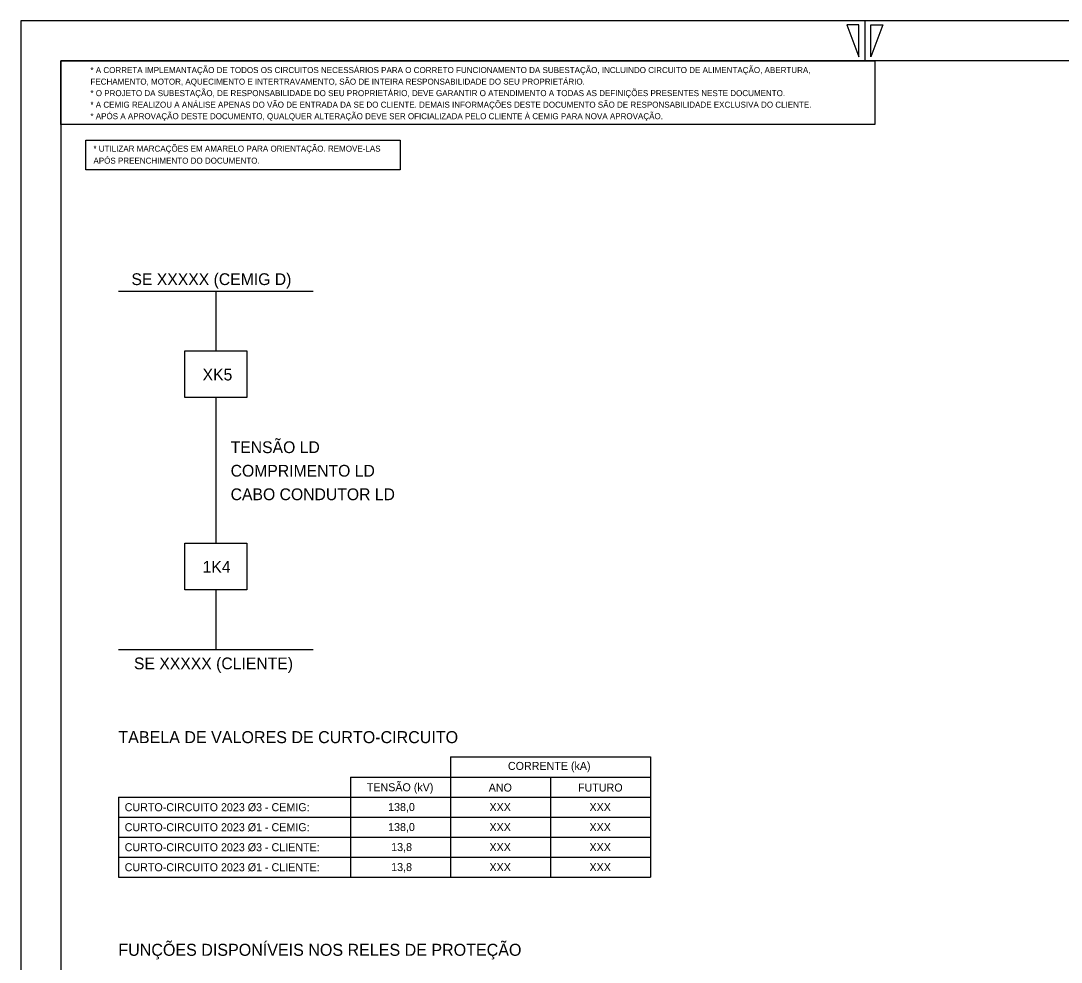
# Model space of a CAD drawing. Extents: x 563 to 1404, y 358 to 952.
# Drawn here: x 562.6 to 822.6, y 716.8 to 952 of the extents above; entities that cross this region are included whole.
import ezdxf

# ---------------------------------------------------------------- set-up
doc = ezdxf.new("R2010")
doc.units = 0
doc.layers.add('New Level (0)', color=7, linetype='Continuous')

# ---------------------------------------------------------------- blocks, each defined once
blk = doc.blocks.new('POINT_DISPLAY')
blk.add_line((0, 0), (0, 0))

msp = doc.modelspace()

# ---------------------------------------------------------------- linework, layer by layer
for p, q in [((586.96, 884.4), (635.66, 884.4)), ((611.31, 884.4), (611.31, 869.54)), ((611.31, 857.81), (611.31, 821.5)), ((611.31, 809.77), (611.31, 794.9)), ((586.96, 794.9), (635.66, 794.9))]:
    msp.add_line(p, q)
for points in [[(603.54, 869.54), (619.08, 869.54), (619.08, 857.81), (603.54, 857.81)], [(603.54, 821.5), (619.08, 821.5), (619.08, 809.77), (603.54, 809.77)]]:
    msp.add_lwpolyline(points, close=True)
at = {"layer": 'New Level (0)'}
for p, q in [((562.58, 951.96), (562.58, 357.96)), ((1403.58, 951.96), (562.58, 951.96)), ((1403.58, 951.96), (562.58, 951.96)), ((562.58, 951.96), (562.58, 357.96)), ((773.58, 951.96), (773.58, 941.96)), ((772.08, 950.96), (769.08, 950.96)), ((769.08, 950.96), (772.08, 942.96)), ((772.08, 942.96), (772.08, 950.96)), ((775.08, 942.96), (775.08, 950.96)), ((775.08, 950.96), (778.08, 950.96)), ((778.08, 950.96), (775.08, 942.96)), ((572.58, 941.96), (572.58, 367.96)), ((1393.58, 941.96), (572.58, 941.96)), ((572.58, 941.96), (572.58, 367.96)), ((670.01, 768.04), (670.01, 738.04)), ((670.01, 768.04), (720.01, 768.04)), ((720.01, 768.04), (720.01, 738.04)), ((645.01, 763.04), (645.01, 738.04)), ((645.01, 763.04), (720.01, 763.04)), ((695.01, 763.04), (695.01, 738.04)), ((586.96, 758.04), (720.01, 758.04)), ((586.96, 758.04), (586.96, 738.04)), ((586.96, 753.04), (720.01, 753.04)), ((586.96, 748.04), (720.01, 748.04)), ((586.96, 743.04), (720.01, 743.04)), ((586.96, 738.04), (720.01, 738.04))]:
    msp.add_line(p, q, dxfattribs=at)
for points in [[(572.58, 941.96), (776.08, 941.96), (776.08, 926.09), (572.58, 926.09)], [(578.87, 922.15), (657.43, 922.15), (657.43, 914.73), (578.87, 914.73)]]:
    msp.add_lwpolyline(points, close=True, dxfattribs=at)

# ---------------------------------------------------------------- block references
msp.add_blockref('POINT_DISPLAY', (670.01, 758.04), dxfattribs=at)

# ---------------------------------------------------------------- texts
for s, height, p in [('* UTILIZAR MARCAÇÕES EM AMARELO PARA ORIENTAÇÃO. REMOVE-LAS ', 1.5, (580.73, 919.27)), ('APÓS PREENCHIMENTO DO DOCUMENTO.', 1.5, (580.73, 916.27)), ('SE XXXXX (CEMIG D)', 2.94, (590.23, 885.94)), ('XK5', 2.94, (608.02, 862.11)), ('TENSÃO LD ', 2.94, (615.03, 843.96)), ('COMPRIMENTO LD', 2.94, (615.03, 838.08)), ('CABO CONDUTOR LD ', 2.94, (615.03, 832.2)), ('1K4', 2.94, (608.02, 814.07)), ('SE XXXXX (CLIENTE)', 2.94, (590.86, 789.95)), ('TABELA DE VALORES DE CURTO-CIRCUITO', 3, (586.96, 771.5)), ('CORRENTE (kA)', 2, (684.34, 764.81)), ('TENSÃO (kV)', 2, (649.07, 759.48)), ('ANO', 2, (679.54, 759.4)), ('FUTURO', 2, (701.87, 759.4)), ('CURTO-CIRCUITO 2023 Ø3 - CEMIG:', 2, (588.55, 754.5)), ('138,0', 2, (654.39, 754.54)), ('XXX', 2, (679.73, 754.54)), ('XXX', 2, (704.73, 754.54)), ('CURTO-CIRCUITO 2023 Ø1 - CEMIG:', 2, (588.55, 749.5)), ('138,0', 2, (654.39, 749.54)), ('XXX', 2, (679.73, 749.54)), ('XXX', 2, (704.73, 749.54)), ('CURTO-CIRCUITO 2023 Ø3 - CLIENTE:', 2, (588.55, 744.5)), ('13,8', 2, (655.16, 744.54)), ('XXX', 2, (679.73, 744.54)), ('XXX', 2, (704.73, 744.54)), ('CURTO-CIRCUITO 2023 Ø1 - CLIENTE:', 2, (588.55, 739.5)), ('13,8', 2, (655.16, 739.54)), ('XXX', 2, (679.73, 739.54)), ('XXX', 2, (704.73, 739.54)), ('FUNÇÕES DISPONÍVEIS NOS RELES DE PROTEÇÃO', 3, (586.96, 718.37))]:
    msp.add_text(s, height=height).set_placement(p)
for s, p in [('* A CORRETA IMPLEMANTAÇÃO DE TODOS OS CIRCUITOS NECESSÁRIOS PARA O CORRETO FUNCIONAMENTO DA SUBESTAÇÃO, INCLUINDO CIRCUITO DE ALIMENTAÇÃO, ABERTURA,   ', (579.98, 938.9)), ('FECHAMENTO, MOTOR, AQUECIMENTO E INTERTRAVAMENTO, SÃO DE INTEIRA RESPONSABILIDADE DO SEU PROPRIETÁRIO.', (579.98, 936.02)), ('* O PROJETO DA SUBESTAÇÃO, DE RESPONSABILIDADE DO SEU PROPRIETÁRIO, DEVE GARANTIR O ATENDIMENTO A TODAS AS DEFINIÇÕES PRESENTES NESTE DOCUMENTO.', (579.98, 933.14)), ('* A CEMIG REALIZOU A ANÁLISE APENAS DO VÃO DE ENTRADA DA SE DO CLIENTE. DEMAIS INFORMAÇÕES DESTE DOCUMENTO SÃO DE RESPONSABILIDADE EXCLUSIVA DO CLIENTE.', (579.98, 930.26)), ('* APÓS A APROVAÇÃO DESTE DOCUMENTO, QUALQUER ALTERAÇÃO DEVE SER OFICIALIZADA PELO CLIENTE À CEMIG PARA NOVA APROVAÇÃO.', (579.98, 927.38))]:
    msp.add_text(s, height=1.5, dxfattribs=at).set_placement(p)

doc.saveas('drawing.dxf')
